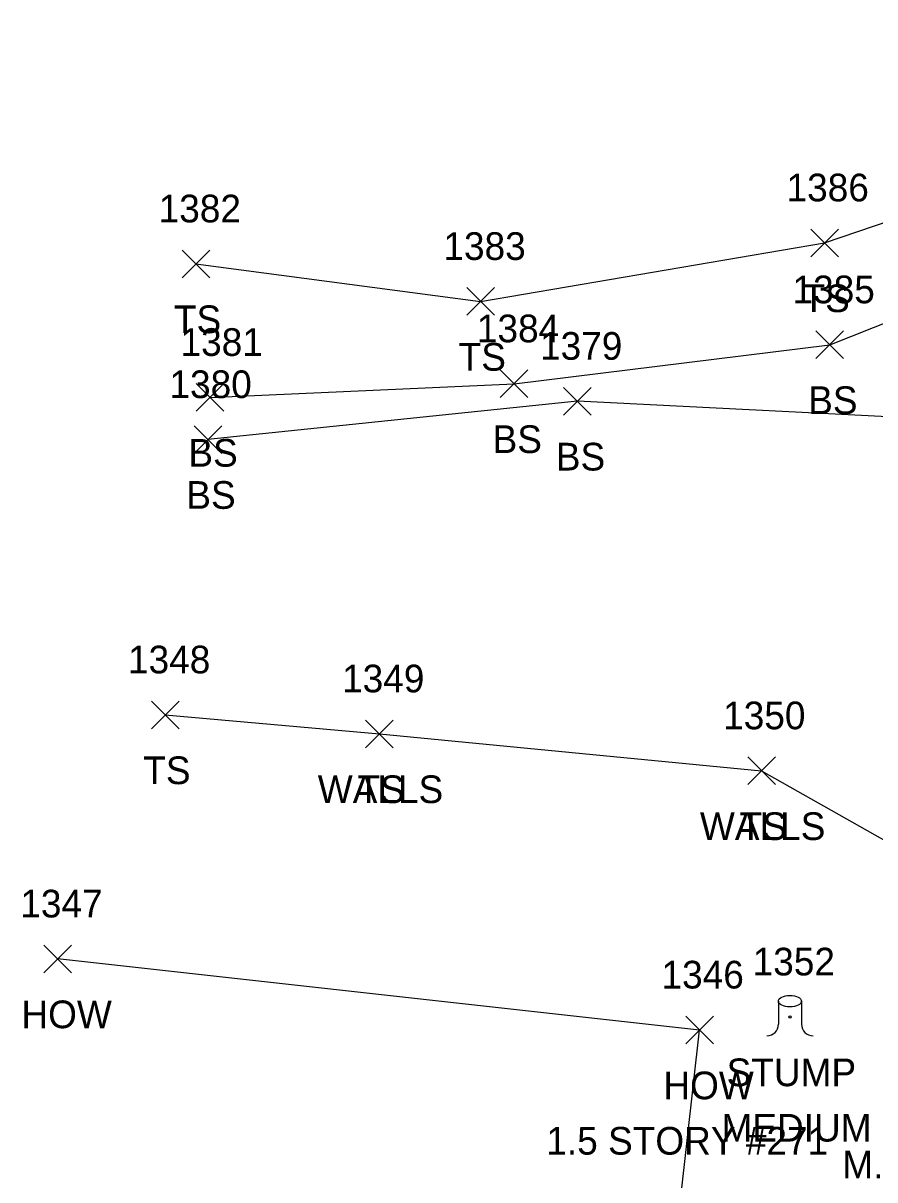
# Model space of a CAD drawing. Extents: x 1653908 to 1654393, y 539913 to 544256.
# Drawn here: x 1653953.6 to 1654015.1, y 541473.4 to 541556.9 of the extents above; entities that cross this region are included whole.
import ezdxf

# ---------------------------------------------------------------- set-up
doc = ezdxf.new("R2010")
doc.units = 0
for name, color, linetype in [('L_A', 7, 'Continuous'), ('L_C', 7, 'Continuous'), ('L_I', 7, 'Continuous'), ('L_TIC', 7, 'Continuous'), ('LBC', 7, 'Continuous'), ('LELB', 7, 'Continuous'), ('LTS', 7, 'Continuous'), ('LWS', 7, 'Continuous')]:
    doc.layers.add(name, color=color, linetype=linetype)

msp = doc.modelspace()

# ---------------------------------------------------------------- linework, layer by layer
at = {"layer": 'L_TIC'}
for points in [[(1654010.467, 541540.066), (1654012.467, 541542.066)], [(1654012.467, 541540.066), (1654010.467, 541542.066)], [(1653965.039, 541538.547), (1653967.039, 541540.547)], [(1653967.039, 541538.547), (1653965.039, 541540.547)], [(1653985.615, 541535.835), (1653987.615, 541537.835)], [(1653987.615, 541535.835), (1653985.615, 541537.835)], [(1654010.842, 541532.704), (1654012.842, 541534.704)], [(1654012.842, 541532.704), (1654010.842, 541534.704)], [(1653988.035, 541529.886), (1653990.035, 541531.886)], [(1653990.035, 541529.886), (1653988.035, 541531.886)], [(1653966.053, 541528.902), (1653968.053, 541530.902)], [(1653968.053, 541528.902), (1653966.053, 541530.902)], [(1653992.606, 541528.624), (1653994.606, 541530.624)], [(1653994.606, 541528.624), (1653992.606, 541530.624)], [(1653965.905, 541525.856), (1653967.905, 541527.856)], [(1653967.905, 541525.856), (1653965.905, 541527.856)], [(1653962.824, 541505.97), (1653964.824, 541507.97)], [(1653964.824, 541505.97), (1653962.824, 541507.97)], [(1653978.301, 541504.599), (1653980.301, 541506.599)], [(1653980.301, 541504.599), (1653978.301, 541506.599)], [(1653978.301, 541504.599), (1653980.301, 541506.599)], [(1653980.301, 541504.599), (1653978.301, 541506.599)], [(1654005.915, 541501.932), (1654007.915, 541503.932)], [(1654007.915, 541501.932), (1654005.915, 541503.932)], [(1654005.915, 541501.932), (1654007.915, 541503.932)], [(1654007.915, 541501.932), (1654005.915, 541503.932)], [(1653955.042, 541488.339), (1653957.042, 541490.339)], [(1653957.042, 541488.339), (1653955.042, 541490.339)], [(1654001.431, 541483.206), (1654003.431, 541485.206)], [(1654003.431, 541483.206), (1654001.431, 541485.206)]]:
    msp.add_lwpolyline(points, dxfattribs=at)
at = {"layer": 'LBC'}
msp.add_lwpolyline([(1653994.454, 541444.255), (1653997.854, 541443.729), (1653999.746, 541459.658), (1654000.621, 541468.041), (1654002.431, 541484.206), (1653956.042, 541489.339)], dxfattribs=at)
at = {"layer": 'LELB'}
for points in [[(1654006.915, 541502.932), (1654019.572, 541495.774), (1654029.506, 541494.378), (1654034.561, 541492.875), (1654037.227, 541522.669), (1654040.253, 541562.932)], [(1653966.039, 541539.547), (1653986.615, 541536.835), (1654011.467, 541541.066), (1654024.718, 541545.57), (1654031.605, 541544.072)], [(1653967.053, 541529.902), (1653989.035, 541530.886), (1654011.842, 541533.704), (1654025.976, 541539.317), (1654033.701, 541541.772), (1654034.003, 541545.075)], [(1654027.089, 541497.132), (1654026.077, 541497.129), (1654024.971, 541513.486), (1654021.279, 541528.225), (1653993.606, 541529.624), (1653966.905, 541526.856)], [(1653963.824, 541506.97), (1653979.301, 541505.599)]]:
    msp.add_lwpolyline(points, dxfattribs=at)
at = {"layer": 'LTS'}
for p, q in [((1654008.132, 541486.29), (1654008.132, 541484.623)), ((1654009.799, 541486.123), (1654009.799, 541486.29)), ((1654009.799, 541486.29), (1654009.799, 541484.623)), ((1654008.966, 541485.148), (1654008.966, 541485.148)), ((1654008.966, 541485.148), (1654008.966, 541485.148)), ((1654008.966, 541485.123), (1654008.966, 541485.123))]:
    msp.add_line(p, q, dxfattribs=at)
msp.add_circle((1654008.966, 541485.148), 0.0833, dxfattribs=at)
for centre, start, end in [((1654007.299, 541484.623), 270, 360), ((1654010.632, 541484.623), 180, 270)]:
    msp.add_arc(centre, 0.833, start, end, dxfattribs=at)
msp.add_ellipse((1654008.966, 541486.29), major_axis=(-0.833, 0), ratio=0.5, dxfattribs=at)
at = {"layer": 'LWS'}
msp.add_lwpolyline([(1653979.301, 541505.599), (1654006.915, 541502.932)], dxfattribs=at)

# ---------------------------------------------------------------- texts
at = {"layer": 'L_A'}
for s, p in [('TS', (1654009.877, 541536.066)), ('TS', (1653964.448, 541534.547)), ('TS', (1653985.024, 541531.835)), ('BS', (1654010.283, 541528.704)), ('BS', (1653987.476, 541525.886)), ('BS', (1653965.494, 541524.902)), ('BS', (1653992.047, 541524.624)), ('BS', (1653965.346, 541521.856)), ('TS', (1653962.234, 541501.97)), ('WALLS', (1653974.844, 541500.599)), ('TS', (1653977.71, 541500.599)), ('WALLS', (1654002.459, 541497.932)), ('TS', (1654005.325, 541497.932)), ('HOW', (1653953.427, 541484.339)), ('STUMP', (1654004.387, 541480.15)), ('HOW', (1653999.817, 541479.206))]:
    msp.add_text(s, height=2, dxfattribs=at).set_placement(p)
at = {"layer": 'L_C'}
for s, p in [('MEDIUM', (1654004.017, 541476.15)), ('1.5 STORY #271', (1653991.36, 541475.206)), ('M. MAPLE', (1654012.749, 541473.482))]:
    msp.add_text(s, height=2, dxfattribs=at).set_placement(p)
at = {"layer": 'L_I'}
for s, p in [('1386', (1654008.719, 541544.066)), ('1382', (1653963.346, 541542.547)), ('1383', (1653983.922, 541539.835)), ('1385', (1654009.149, 541536.704)), ('1384', (1653986.343, 541533.886)), ('1381', (1653964.927, 541532.902)), ('1379', (1653990.905, 541532.624)), ('1380', (1653964.126, 541529.856)), ('1348', (1653961.131, 541509.97)), ('1349', (1653976.6, 541508.599)), ('1349', (1653976.6, 541508.599)), ('1350', (1654004.136, 541505.932)), ('1350', (1654004.136, 541505.932)), ('1347', (1653953.349, 541492.339)), ('1352', (1654006.269, 541488.15)), ('1346', (1653999.683, 541487.206))]:
    msp.add_text(s, height=2, dxfattribs=at).set_placement(p)

doc.saveas('drawing.dxf')
